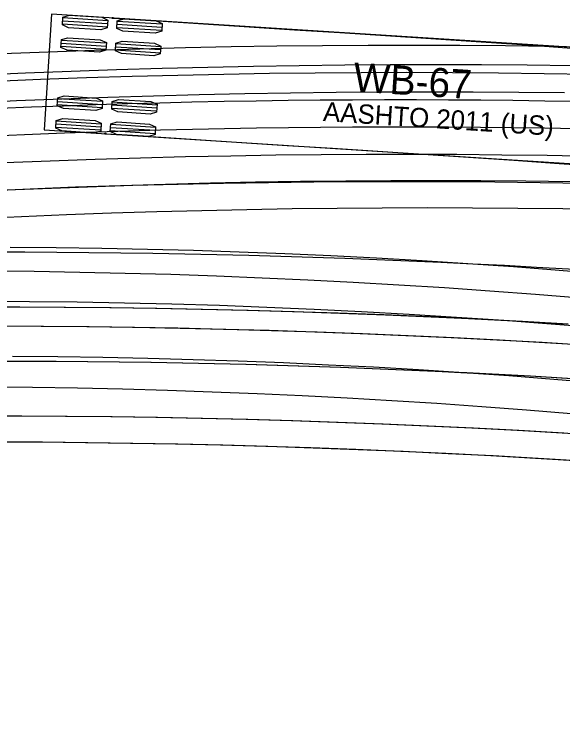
# Model space of a CAD drawing. Extents: x 916040 to 917457, y 328936 to 330267.
# Drawn here: x 916245.1 to 916285.4, y 329686.1 to 329737.8 of the extents above; entities that cross this region are included whole.
import ezdxf

# ---------------------------------------------------------------- set-up
doc = ezdxf.new("R2010")
doc.units = 0
for name, color, linetype in [('EB_LeftontoManchester_WB67', 7, 'Continuous'), ('EB_LeftontoManchester_WB67_v2', 7, 'Continuous'), ('EB_RightontoSaco_WB67_v2', 7, 'Continuous'), ('EB_Thru_WB67', 7, 'Continuous'), ('EB_Thru_WB67_v2', 7, 'Continuous'), ('NB_LeftontoRoute25_WB67', 7, 'Continuous'), ('SB_RightontoRoute25_WB67_v2', 7, 'Continuous'), ('WB_Thru_WB67', 7, 'Continuous')]:
    doc.layers.add(name, color=color, linetype=linetype)

msp = doc.modelspace()

# ---------------------------------------------------------------- linework, layer by layer
at = {"layer": 'EB_LeftontoManchester_WB67'}
for points in [[(916244.848, 329720.728), (916248.207, 329720.699), (916251.567, 329720.65), (916254.925, 329720.58), (916258.284, 329720.49), (916261.641, 329720.38), (916264.998, 329720.249), (916268.355, 329720.098), (916271.71, 329719.926), (916275.064, 329719.734), (916278.417, 329719.522), (916281.768, 329719.29), (916285.119, 329719.037), (916288.467, 329718.764)], [(916243.251, 329718.987), (916246.598, 329718.95), (916249.945, 329718.894), (916253.291, 329718.819), (916256.637, 329718.725), (916259.983, 329718.611), (916263.328, 329718.478), (916266.671, 329718.326), (916270.015, 329718.154), (916273.356, 329717.963), (916276.697, 329717.752), (916280.037, 329717.521), (916283.375, 329717.271), (916286.711, 329717.001)], [(916245.019, 329712.731), (916248.331, 329712.701), (916251.642, 329712.651), (916254.952, 329712.581), (916258.262, 329712.491), (916261.572, 329712.381), (916264.881, 329712.251), (916268.189, 329712.1), (916271.495, 329711.93), (916274.801, 329711.74), (916278.106, 329711.529), (916281.409, 329711.299), (916284.711, 329711.048), (916288.011, 329710.778)], [(916243.184, 329710.487), (916246.482, 329710.451), (916249.781, 329710.395), (916253.079, 329710.322), (916256.376, 329710.229), (916259.672, 329710.117), (916262.968, 329709.986), (916266.262, 329709.836), (916269.556, 329709.666), (916272.848, 329709.478), (916276.139, 329709.27), (916279.429, 329709.043), (916282.717, 329708.797), (916286.004, 329708.531)]]:
    msp.add_lwpolyline(points, dxfattribs=at)
msp.add_arc((916241.758, 329166.738), 550, 75.00607, 98.25153, dxfattribs=at)
at = {"layer": 'EB_LeftontoManchester_WB67_v2'}
for points in [[(916242.099, 329716.338), (916245.449, 329716.338), (916248.8, 329716.322), (916252.15, 329716.29), (916255.5, 329716.243), (916258.85, 329716.179), (916262.2, 329716.1), (916265.549, 329716.005), (916268.897, 329715.894), (916272.245, 329715.767), (916275.593, 329715.624), (916278.939, 329715.465), (916282.285, 329715.291), (916285.63, 329715.101)], [(916243.783, 329714.949), (916247.126, 329714.933), (916250.469, 329714.901), (916253.812, 329714.855), (916257.154, 329714.793), (916260.497, 329714.715), (916263.838, 329714.622), (916267.18, 329714.514), (916270.521, 329714.391), (916273.861, 329714.251), (916277.201, 329714.097), (916280.54, 329713.927), (916283.878, 329713.741), (916287.215, 329713.54)], [(916242.289, 329708.341), (916245.601, 329708.34), (916248.914, 329708.323), (916252.226, 329708.291), (916255.539, 329708.243), (916258.851, 329708.18), (916262.162, 329708.101), (916265.474, 329708.006), (916268.784, 329707.895), (916272.095, 329707.769), (916275.404, 329707.627), (916278.713, 329707.469), (916282.021, 329707.296), (916285.328, 329707.107), (916288.635, 329706.902)], [(916243.763, 329706.449), (916247.067, 329706.433), (916250.371, 329706.402), (916253.675, 329706.356), (916256.979, 329706.294), (916260.282, 329706.218), (916263.585, 329706.126), (916266.887, 329706.019), (916270.189, 329705.897), (916273.49, 329705.76), (916276.79, 329705.607), (916280.089, 329705.439), (916283.388, 329705.255), (916286.685, 329705.056)]]:
    msp.add_lwpolyline(points, dxfattribs=at)
msp.add_arc((916243.774, 329008.841), 703.5, 74.309906, 98.540079, dxfattribs=at)
at = {"layer": 'EB_RightontoSaco_WB67_v2'}
for points in [[(916244.848, 329720.728), (916248.207, 329720.699), (916251.567, 329720.65), (916254.925, 329720.58), (916258.284, 329720.49), (916261.641, 329720.38), (916264.998, 329720.249), (916268.355, 329720.098), (916271.71, 329719.926), (916275.064, 329719.734), (916278.417, 329719.522), (916281.768, 329719.29), (916285.119, 329719.037), (916288.467, 329718.764)], [(916243.251, 329718.987), (916246.598, 329718.95), (916249.945, 329718.894), (916253.291, 329718.819), (916256.637, 329718.725), (916259.983, 329718.611), (916263.328, 329718.478), (916266.671, 329718.326), (916270.015, 329718.154), (916273.356, 329717.963), (916276.697, 329717.752), (916280.037, 329717.521), (916283.375, 329717.271), (916286.711, 329717.001)], [(916245.019, 329712.731), (916248.331, 329712.701), (916251.642, 329712.651), (916254.952, 329712.581), (916258.262, 329712.491), (916261.572, 329712.381), (916264.881, 329712.251), (916268.189, 329712.1), (916271.495, 329711.93), (916274.801, 329711.74), (916278.106, 329711.529), (916281.409, 329711.299), (916284.711, 329711.048), (916288.011, 329710.778)], [(916243.184, 329710.487), (916246.482, 329710.451), (916249.781, 329710.395), (916253.079, 329710.322), (916256.376, 329710.229), (916259.672, 329710.117), (916262.968, 329709.986), (916266.262, 329709.836), (916269.556, 329709.666), (916272.848, 329709.478), (916276.139, 329709.27), (916279.429, 329709.043), (916282.717, 329708.797), (916286.004, 329708.531)]]:
    msp.add_lwpolyline(points, dxfattribs=at)
msp.add_arc((916241.758, 329166.738), 550, 75.00607, 98.25153, dxfattribs=at)
at = {"layer": 'EB_Thru_WB67'}
for points in [[(916244.848, 329720.728), (916248.207, 329720.699), (916251.567, 329720.65), (916254.925, 329720.58), (916258.284, 329720.49), (916261.641, 329720.38), (916264.998, 329720.249), (916268.355, 329720.098), (916271.71, 329719.926), (916275.064, 329719.734), (916278.417, 329719.522), (916281.768, 329719.29), (916285.119, 329719.037), (916288.467, 329718.764)], [(916243.251, 329718.987), (916246.598, 329718.95), (916249.945, 329718.894), (916253.291, 329718.819), (916256.637, 329718.725), (916259.983, 329718.611), (916263.328, 329718.478), (916266.671, 329718.326), (916270.015, 329718.154), (916273.356, 329717.963), (916276.697, 329717.752), (916280.037, 329717.521), (916283.375, 329717.271), (916286.711, 329717.001)], [(916245.019, 329712.731), (916248.331, 329712.701), (916251.642, 329712.651), (916254.952, 329712.581), (916258.262, 329712.491), (916261.572, 329712.381), (916264.881, 329712.251), (916268.189, 329712.1), (916271.495, 329711.93), (916274.801, 329711.74), (916278.106, 329711.529), (916281.409, 329711.299), (916284.711, 329711.048), (916288.011, 329710.778)], [(916243.184, 329710.487), (916246.482, 329710.451), (916249.781, 329710.395), (916253.079, 329710.322), (916256.376, 329710.229), (916259.672, 329710.117), (916262.968, 329709.986), (916266.262, 329709.836), (916269.556, 329709.666), (916272.848, 329709.478), (916276.139, 329709.27), (916279.429, 329709.043), (916282.717, 329708.797), (916286.004, 329708.531)]]:
    msp.add_lwpolyline(points, dxfattribs=at)
for centre, radius, start, end in [((916243.774, 329008.841), 711.5, 74.309906, 98.540079), ((916241.758, 329166.738), 550, 75.00607, 98.25153)]:
    msp.add_arc(centre, radius, start, end, dxfattribs=at)
at = {"layer": 'EB_Thru_WB67_v2'}
for points in [[(916242.193, 329716.338), (916245.546, 329716.338), (916248.9, 329716.321), (916252.253, 329716.289), (916255.606, 329716.241), (916258.959, 329716.177), (916262.312, 329716.097), (916265.664, 329716.001), (916269.016, 329715.889), (916272.367, 329715.762), (916275.717, 329715.618), (916279.067, 329715.459), (916282.416, 329715.284), (916285.764, 329715.093)], [(916243.937, 329714.949), (916247.283, 329714.932), (916250.629, 329714.9), (916253.975, 329714.852), (916257.321, 329714.789), (916260.666, 329714.711), (916264.011, 329714.617), (916267.355, 329714.508), (916270.699, 329714.384), (916274.043, 329714.243), (916277.385, 329714.088), (916280.727, 329713.917), (916284.068, 329713.73), (916287.408, 329713.528)], [(916242.382, 329708.341), (916245.697, 329708.34), (916249.013, 329708.323), (916252.328, 329708.29), (916255.644, 329708.242), (916258.959, 329708.177), (916262.273, 329708.098), (916265.588, 329708.002), (916268.901, 329707.891), (916272.215, 329707.764), (916275.527, 329707.621), (916278.839, 329707.463), (916282.15, 329707.289), (916285.46, 329707.099)], [(916243.916, 329706.449), (916247.223, 329706.432), (916250.53, 329706.4), (916253.837, 329706.353), (916257.144, 329706.291), (916260.45, 329706.214), (916263.755, 329706.121), (916267.06, 329706.013), (916270.365, 329705.89), (916273.669, 329705.752), (916276.972, 329705.598), (916280.275, 329705.429), (916283.576, 329705.244), (916286.877, 329705.044)]]:
    msp.add_lwpolyline(points, dxfattribs=at)
msp.add_arc((916243.774, 329008.841), 703.5, 74.315114, 98.540079, dxfattribs=at)
at = {"layer": 'NB_LeftontoRoute25_WB67'}
for p, q in [((916247.875, 329737.805), (916247.332, 329729.323)), ((916300.767, 329734.419), (916247.875, 329737.805)), ((916251.988, 329737.083), (916248.694, 329737.294)), ((916252.002, 329737.311), (916248.709, 329737.522)), ((916251.973, 329736.854), (916248.68, 329737.065)), ((916255.965, 329736.598), (916252.671, 329736.809)), ((916255.979, 329736.827), (916252.686, 329737.038)), ((916255.994, 329737.056), (916252.701, 329737.267)), ((916251.897, 329735.665), (916248.604, 329735.876)), ((916251.867, 329735.207), (916248.574, 329735.418)), ((916251.882, 329735.436), (916248.589, 329735.647)), ((916255.874, 329735.18), (916252.581, 329735.391)), ((916255.889, 329735.409), (916252.595, 329735.62)), ((916255.859, 329734.952), (916252.566, 329735.163)), ((916251.623, 329731.39), (916248.33, 329731.601)), ((916251.594, 329730.933), (916248.301, 329731.144)), ((916251.608, 329731.161), (916248.315, 329731.372)), ((916255.6, 329730.906), (916252.307, 329731.117)), ((916255.615, 329731.135), (916252.322, 329731.345)), ((916255.586, 329730.677), (916252.292, 329730.888)), ((916251.503, 329729.515), (916248.21, 329729.726)), ((916251.518, 329729.744), (916248.224, 329729.954)), ((916255.509, 329729.488), (916252.216, 329729.699)), ((916247.332, 329729.323), (916300.224, 329725.936)), ((916251.488, 329729.286), (916248.195, 329729.497)), ((916255.48, 329729.031), (916252.187, 329729.241)), ((916255.495, 329729.259), (916252.202, 329729.47))]:
    msp.add_line(p, q, dxfattribs=at)
for points in [[(916252.006, 329737.368), (916251.969, 329736.797), (916251.497, 329736.655), (916249.126, 329736.807), (916248.676, 329737.008), (916248.713, 329737.579), (916249.185, 329737.721), (916251.556, 329737.57)], [(916255.998, 329737.112), (916255.961, 329736.542), (916255.489, 329736.399), (916253.118, 329736.551), (916252.668, 329736.753), (916252.704, 329737.323), (916253.176, 329737.466), (916255.548, 329737.314)], [(916251.9, 329735.721), (916251.864, 329735.151), (916251.392, 329735.008), (916249.021, 329735.16), (916248.571, 329735.362), (916248.607, 329735.932), (916249.079, 329736.075), (916251.45, 329735.923)], [(916255.892, 329735.466), (916255.856, 329734.895), (916255.384, 329734.753), (916253.012, 329734.904), (916252.562, 329735.106), (916252.599, 329735.677), (916253.071, 329735.819), (916255.442, 329735.667)], [(916251.627, 329731.447), (916251.59, 329730.876), (916251.118, 329730.734), (916248.747, 329730.885), (916248.297, 329731.087), (916248.333, 329731.658), (916248.806, 329731.8), (916251.177, 329731.648)], [(916255.619, 329731.191), (916255.582, 329730.62), (916255.11, 329730.478), (916252.739, 329730.63), (916252.289, 329730.831), (916252.325, 329731.402), (916252.797, 329731.545), (916255.168, 329731.393)], [(916251.521, 329729.8), (916251.485, 329729.229), (916251.013, 329729.087), (916248.641, 329729.239), (916248.191, 329729.44), (916248.228, 329730.011), (916248.7, 329730.154), (916251.071, 329730.002)], [(916255.513, 329729.545), (916255.477, 329728.974), (916255.004, 329728.831), (916252.633, 329728.983), (916252.183, 329729.185), (916252.22, 329729.756), (916252.692, 329729.898), (916255.063, 329729.746)]]:
    msp.add_lwpolyline(points, close=True, dxfattribs=at)
for points in [[(916252.366, 329737.518), (916255.699, 329737.304), (916259.032, 329737.091), (916262.365, 329736.877), (916265.698, 329736.662), (916269.032, 329736.447), (916272.366, 329736.23), (916275.7, 329736.011), (916279.035, 329735.79), (916282.37, 329735.565), (916285.706, 329735.338), (916289.041, 329735.106), (916292.377, 329734.87), (916295.713, 329734.629), (916299.049, 329734.382), (916302.385, 329734.13), (916305.72, 329733.871), (916309.056, 329733.606), (916312.391, 329733.333), (916315.726, 329733.053), (916319.061, 329732.765), (916322.395, 329732.469), (916325.729, 329732.165)], [(916251.823, 329729.035), (916255.156, 329728.822), (916258.488, 329728.608), (916261.82, 329728.394), (916265.151, 329728.18), (916268.482, 329727.965), (916271.812, 329727.748), (916275.141, 329727.529), (916278.469, 329727.309), (916281.796, 329727.085), (916285.122, 329726.858), (916288.448, 329726.627), (916291.772, 329726.391), (916295.094, 329726.151), (916298.416, 329725.906), (916301.737, 329725.655), (916305.056, 329725.397), (916308.374, 329725.133), (916311.691, 329724.862), (916315.006, 329724.584), (916318.321, 329724.298), (916321.634, 329724.004), (916324.945, 329723.701)]]:
    msp.add_lwpolyline(points, dxfattribs=at)
for centre in [(916252.366, 329737.518), (916251.823, 329729.035)]:
    msp.add_circle(centre, 0.0417, dxfattribs=at)
at = {"layer": 'SB_RightontoRoute25_WB67_v2'}
for points in [[(916287.372, 329733.371), (916284.014, 329733.431), (916280.656, 329733.474), (916277.297, 329733.501), (916273.939, 329733.511), (916270.58, 329733.505), (916267.221, 329733.482), (916263.863, 329733.443), (916260.504, 329733.388), (916257.146, 329733.315), (916253.788, 329733.227), (916250.431, 329733.121), (916247.074, 329733), (916243.718, 329732.861)], [(916285.503, 329732.026), (916282.153, 329732.063), (916278.802, 329732.085), (916275.451, 329732.091), (916272.1, 329732.082), (916268.749, 329732.056), (916265.398, 329732.015), (916262.047, 329731.958), (916258.697, 329731.886), (916255.347, 329731.797), (916251.997, 329731.693), (916248.649, 329731.572), (916245.3, 329731.436), (916241.952, 329731.283)], [(916287.04, 329725.378), (916283.72, 329725.437), (916280.4, 329725.479), (916277.08, 329725.504), (916273.76, 329725.514), (916270.44, 329725.507), (916267.12, 329725.484), (916263.8, 329725.444), (916260.481, 329725.388), (916257.162, 329725.316), (916253.843, 329725.227), (916250.525, 329725.122), (916247.207, 329725.001), (916243.891, 329724.864)], [(916288.698, 329723.474), (916285.387, 329723.527), (916282.076, 329723.563), (916278.764, 329723.585), (916275.453, 329723.591), (916272.142, 329723.582), (916268.831, 329723.557), (916265.52, 329723.516), (916262.209, 329723.46), (916258.899, 329723.388), (916255.59, 329723.301), (916252.281, 329723.197), (916248.972, 329723.078), (916245.665, 329722.943), (916242.358, 329722.793)]]:
    msp.add_lwpolyline(points, dxfattribs=at)
msp.add_arc((916273.509, 329050.513), 679, 86.336243, 99.016626, dxfattribs=at)
msp.add_arc((916273.509, 329050.513), 679, 86.336243, 99.016626, dxfattribs=at)
msp.add_arc((916273.509, 329050.513), 679, 86.336243, 99.016626, dxfattribs=at)
at = {"layer": 'WB_Thru_WB67'}
for points in [[(916287.88, 329735.361), (916284.527, 329735.423), (916281.174, 329735.468), (916277.821, 329735.498), (916274.467, 329735.511), (916271.113, 329735.507), (916267.76, 329735.487), (916264.406, 329735.451), (916261.053, 329735.398), (916257.7, 329735.329), (916254.347, 329735.243), (916250.995, 329735.141), (916247.643, 329735.023), (916244.292, 329734.888)], [(916286.111, 329734.012), (916282.766, 329734.053), (916279.42, 329734.078), (916276.074, 329734.087), (916272.728, 329734.082), (916269.382, 329734.06), (916266.036, 329734.023), (916262.69, 329733.97), (916259.345, 329733.901), (916256, 329733.816), (916252.655, 329733.715), (916249.311, 329733.599), (916245.967, 329733.467), (916242.624, 329733.318)], [(916287.543, 329727.368), (916284.228, 329727.429), (916280.913, 329727.473), (916277.598, 329727.501), (916274.283, 329727.513), (916270.968, 329727.509), (916267.653, 329727.489), (916264.338, 329727.452), (916261.023, 329727.399), (916257.709, 329727.329), (916254.395, 329727.244), (916251.082, 329727.142), (916247.769, 329727.024), (916244.457, 329726.89)], [(916285.986, 329725.513), (916282.68, 329725.553), (916279.373, 329725.578), (916276.067, 329725.587), (916272.761, 329725.582), (916269.454, 329725.56), (916266.149, 329725.523), (916262.843, 329725.471), (916259.538, 329725.403), (916256.233, 329725.319), (916252.929, 329725.22), (916249.625, 329725.105), (916246.322, 329724.974), (916243.02, 329724.827)]]:
    msp.add_lwpolyline(points, dxfattribs=at)
msp.add_arc((916273.509, 329050.513), 681, 86.336243, 99.016626, dxfattribs=at)

# ---------------------------------------------------------------- texts
at = {"layer": 'NB_LeftontoRoute25_WB67'}
for s, height, p in [('WB-67', 2.125, (916269.96, 329732.132)), ('AASHTO 2011 (US)', 1.41667, (916267.763, 329729.966))]:
    msp.add_text(s, height=height, rotation=356.3362, dxfattribs=at).set_placement(p)

doc.saveas('drawing.dxf')
